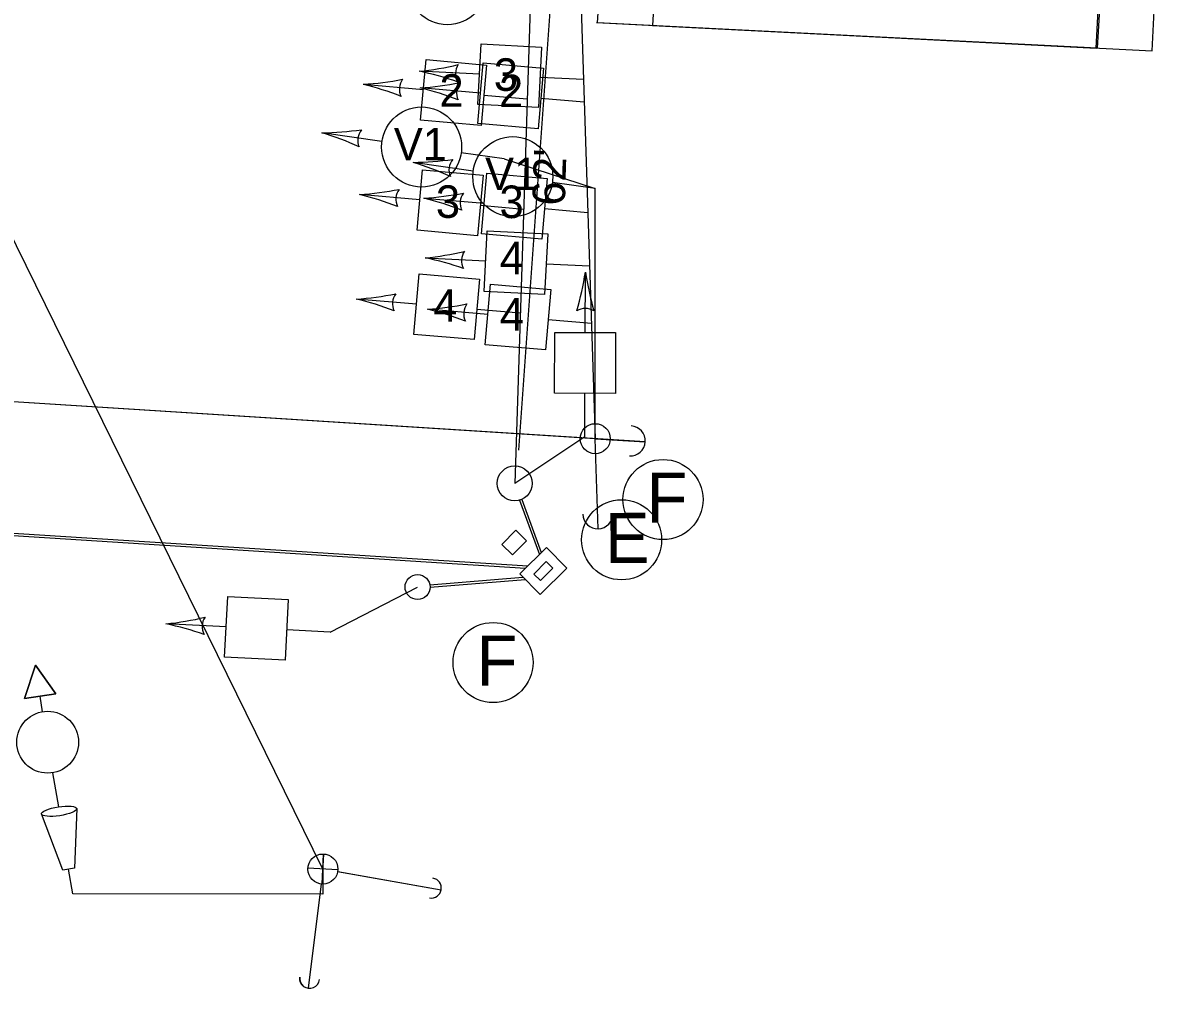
# Model space of a CAD drawing. Extents: x 647787 to 668496, y 640478 to 654412.
# Drawn here: x 659905.1 to 660018.3, y 647331.3 to 647427.8 of the extents above; entities that cross this region are included whole.
import ezdxf

# ---------------------------------------------------------------- set-up
doc = ezdxf.new("R2010")
doc.units = 0
for name, color, linetype in [('T_EXIST_PULL BOX', 7, 'Continuous'), ('TEMP_DETECTION ZONE_STAGE 3', 7, 'Continuous'), ('TEMP_DETECTION_ZONE_STAGE 5', 7, 'Continuous'), ('TEMP_SIGNAL POLES', 7, 'Continuous'), ('TEMP_SIGNAL_HEAD_STAGE 1A', 7, 'Continuous'), ('TEMP_SIGNAL_HEAD_STAGE 2', 7, 'Continuous'), ('TEMP_SIGNAL_HEAD_STAGE 2 SALEM', 7, 'Continuous'), ('TEMP_SIGNAL_HEAD_Stage 3', 7, 'Continuous'), ('TEMP_SIGNAL_HEAD_STAGE 5', 7, 'Continuous'), ('TEMP_SIGNAL_POLES_STAGE 1A', 7, 'Continuous'), ('TEMP_SIGNAL_POLES_STAGE 1B', 7, 'Continuous'), ('TEMP_SIGNAL_POLES_STAGE 2', 7, 'Continuous'), ('TEMP_SIGNAL_POLES_STAGE 3', 7, 'Continuous'), ('TEMP_SIGNAL_POLES_STAGE 5', 7, 'Continuous'), ('TEXT_TEMP_SIGNAL_POLES_STAGE 2', 7, 'Continuous'), ('TEXT_TEMP_SIGNAL_POLES_STAGE 3', 7, 'Continuous'), ('TEXT_TEMP_SIGNAL_POLES_STAGE 4', 7, 'Continuous'), ('TEXT_TEMP_SIGNAL_POLES_STAGE 5', 7, 'Continuous')]:
    doc.layers.add(name, color=color, linetype=linetype)

msp = doc.modelspace()

# ---------------------------------------------------------------- linework, layer by layer
at = {"layer": 'T_EXIST_PULL BOX'}
msp.add_lwpolyline([(659953.01, 647375.66), (659954.41, 647377.09), (659955.48, 647376.03), (659954.07, 647374.61)], close=True, dxfattribs=at)
msp.add_lwpolyline([(659953.01, 647375.66), (659954.41, 647377.09), (659955.48, 647376.03), (659954.07, 647374.61)], close=True, dxfattribs=at)
at = {"layer": 'TEMP_DETECTION ZONE_STAGE 3'}
for p, q in [((659962.57, 647427.78), (659962.91, 647433.77)), ((660012.84, 647431.23), (660012.5, 647425.24)), ((660012.5, 647425.24), (659962.57, 647427.78))]:
    msp.add_line(p, q, dxfattribs=at)
at = {"layer": 'TEMP_DETECTION_ZONE_STAGE 5'}
for p, q in [((659959.03, 647446.07), (659954.66, 647385.09)), ((659959.03, 647446.07), (659954.66, 647385.09)), ((659968.38, 647433.49), (659968.07, 647427.5)), ((660012.4, 647425.25), (660012.7, 647431.24)), ((660018.01, 647424.96), (660018.31, 647430.96)), ((659962.46, 647427.79), (660012.4, 647425.25)), ((659968.07, 647427.5), (660018.01, 647424.96))]:
    msp.add_line(p, q, dxfattribs=at)
at = {"layer": 'TEMP_SIGNAL POLES'}
for p, q in [((659935.12, 647343.23), (659859.63, 647496.63)), ((659935.12, 647343.23), (659859.63, 647496.63)), ((659935.12, 647343.23), (659859.63, 647496.63)), ((659935.12, 647343.23), (659859.63, 647496.63)), ((659935.04, 647341.73), (659935.19, 647344.73)), ((659935.04, 647341.73), (659935.19, 647344.73)), ((659935.04, 647341.73), (659935.19, 647344.73)), ((659935.04, 647341.73), (659935.2, 647344.73)), ((659936.61, 647343.15), (659933.62, 647343.31)), ((659936.61, 647343.15), (659933.62, 647343.31)), ((659936.61, 647343.15), (659933.62, 647343.31)), ((659936.62, 647343.15), (659933.62, 647343.31)), ((659935.12, 647343.23), (659935.12, 647340.73)), ((659935.12, 647343.23), (659935.12, 647340.73)), ((659935.12, 647343.23), (659935.12, 647340.73)), ((659935.12, 647343.23), (659935.12, 647340.73)), ((659936.59, 647342.97), (659946.94, 647341.16)), ((659936.59, 647342.97), (659946.94, 647341.16)), ((659936.59, 647342.97), (659946.94, 647341.16)), ((659936.6, 647342.97), (659946.94, 647341.16)), ((659934.93, 647341.74), (659933.66, 647331.32)), ((659934.93, 647341.74), (659933.66, 647331.32)), ((659934.93, 647341.74), (659933.66, 647331.32)), ((659934.94, 647341.74), (659933.66, 647331.32))]:
    msp.add_line(p, q, dxfattribs=at)
msp.add_lwpolyline([(659935.12, 647340.73), (659910.12, 647340.74)], dxfattribs=at)
msp.add_lwpolyline([(659935.12, 647340.73), (659910.12, 647340.74)], dxfattribs=at)
msp.add_lwpolyline([(659935.12, 647340.73), (659910.12, 647340.74)], dxfattribs=at)
msp.add_lwpolyline([(659935.12, 647340.73), (659910.12, 647340.74)], dxfattribs=at)
msp.add_circle((659935.12, 647343.23), 1.5, dxfattribs=at)
msp.add_circle((659935.12, 647343.23), 1.5, dxfattribs=at)
msp.add_circle((659935.12, 647343.23), 1.5, dxfattribs=at)
msp.add_circle((659935.12, 647343.23), 1.5, dxfattribs=at)
for centre, start, end in [((659945.95, 647341.33), 260.051, 80.051), ((659945.95, 647341.33), 260.051, 80.051), ((659945.95, 647341.33), 260.051, 80.051), ((659945.95, 647341.33), 260.051, 80.051), ((659933.78, 647332.31), 173.0416, 353.0416), ((659933.78, 647332.31), 173.0416, 353.0416), ((659933.78, 647332.31), 173.0416, 353.0416), ((659933.79, 647332.31), 173.0416, 353.0416)]:
    msp.add_arc(centre, 1, start, end, dxfattribs=at)
at = {"layer": 'TEMP_SIGNAL_HEAD_STAGE 1A'}
for p, q in [((659834.95, 647380.92), (659955.37, 647373.29)), ((659834.95, 647380.92), (659955.37, 647373.29)), ((659834.95, 647380.92), (659955.37, 647373.29)), ((659834.96, 647381.17), (659955.61, 647373.52)), ((659834.96, 647381.17), (659955.61, 647373.52)), ((659834.96, 647381.17), (659955.61, 647373.52)), ((659954.77, 647380.07), (659956.75, 647374.65)), ((659954.77, 647380.07), (659956.75, 647374.65)), ((659954.77, 647380.07), (659956.75, 647374.65)), ((659955.01, 647380.16), (659956.94, 647374.85)), ((659955.01, 647380.16), (659956.94, 647374.85)), ((659955.01, 647380.16), (659956.94, 647374.85)), ((659954.79, 647372.71), (659957.45, 647375.35)), ((659954.79, 647372.71), (659957.45, 647375.35)), ((659954.79, 647372.71), (659957.45, 647375.35)), ((659959.5, 647373.28), (659957.45, 647375.35)), ((659959.5, 647373.28), (659957.45, 647375.35)), ((659959.5, 647373.28), (659957.45, 647375.35)), ((659956.2, 647372.7), (659957.44, 647373.94)), ((659956.2, 647372.7), (659957.44, 647373.94)), ((659956.2, 647372.7), (659957.44, 647373.94)), ((659958.09, 647373.29), (659957.44, 647373.94)), ((659958.09, 647373.29), (659957.44, 647373.94)), ((659958.09, 647373.29), (659957.44, 647373.94)), ((659956.84, 647370.64), (659959.5, 647373.28)), ((659956.84, 647370.64), (659959.5, 647373.28)), ((659956.84, 647370.64), (659959.5, 647373.28)), ((659956.85, 647372.05), (659958.09, 647373.29)), ((659956.85, 647372.05), (659958.09, 647373.29)), ((659956.85, 647372.05), (659958.09, 647373.29)), ((659945.81, 647371.63), (659955.11, 647372.39)), ((659945.81, 647371.63), (659955.11, 647372.39)), ((659945.81, 647371.63), (659955.11, 647372.39)), ((659945.83, 647371.38), (659955.34, 647372.16)), ((659945.83, 647371.38), (659955.34, 647372.16)), ((659945.83, 647371.38), (659955.34, 647372.16)), ((659956.84, 647370.64), (659954.79, 647372.71)), ((659956.84, 647370.64), (659954.79, 647372.71)), ((659956.84, 647370.64), (659954.79, 647372.71)), ((659956.85, 647372.05), (659956.2, 647372.7)), ((659956.85, 647372.05), (659956.2, 647372.7)), ((659956.85, 647372.05), (659956.2, 647372.7))]:
    msp.add_line(p, q, dxfattribs=at)
at = {"layer": 'TEMP_SIGNAL_HEAD_STAGE 2'}
for p, q in [((659950.76, 647422.62), (659944.73, 647422.93)), ((659961.16, 647422.09), (659956.82, 647422.31)), ((659950.14, 647412.96), (659944.13, 647413.82)), ((659962.34, 647411.22), (659958.06, 647411.83)), ((659962.34, 647386.22), (659962.34, 647411.22)), ((659951.38, 647403.97), (659945.35, 647404.27)), ((659961.78, 647403.44), (659957.43, 647403.66))]:
    msp.add_line(p, q, dxfattribs=at)
for points in [[(659956.97, 647425.34), (659956.67, 647419.29), (659950.61, 647419.59), (659950.92, 647425.65)], [(659957.59, 647406.69), (659957.28, 647400.63), (659951.23, 647400.94), (659951.53, 647407)]]:
    msp.add_lwpolyline(points, close=True, dxfattribs=at)
msp.add_circle((659954.1, 647412.4), 4, dxfattribs=at)
for centre, radius, start, end in [((659941.8, 647452.25), 29.47, 275.7037, 283.4418), ((659938.85, 647394.05), 29.47, 70.749, 78.4871), ((659949.99, 647422.66), 1.63, 145.2481, 208.9427), ((659943.87, 647443.29), 29.47, 270.5102, 278.2483), ((659935.66, 647385.59), 29.47, 65.5545, 73.2926), ((659949.35, 647413.07), 1.63, 140.0435, 203.7381), ((659942.42, 647433.6), 29.47, 275.7037, 283.4418), ((659950.61, 647404.01), 1.63, 145.2481, 208.9427), ((659939.46, 647375.4), 29.47, 70.749, 78.4871)]:
    msp.add_arc(centre, radius, start, end, dxfattribs=at)
at = {"layer": 'TEMP_SIGNAL_HEAD_STAGE 2 SALEM'}
for points in [[(659908.42, 647360.73), (659905.3, 647360.25), (659906.38, 647363.59), (659908.42, 647360.73)], [(659908.42, 647360.73), (659905.3, 647360.25), (659906.38, 647363.59), (659908.42, 647360.73)], [(659907.1, 647358.94), (659906.86, 647360.49)], [(659907.1, 647358.94), (659906.86, 647360.49)], [(659908.11, 647352.85), (659908.68, 647349.44)], [(659908.11, 647352.85), (659908.68, 647349.44)], [(659910.52, 647349.27), (659910.29, 647343.3)], [(659910.52, 647349.27), (659910.29, 647343.3)], [(659909.14, 647343.12), (659906.98, 647348.73)], [(659909.14, 647343.12), (659906.98, 647348.73)], [(659910.29, 647343.3), (659909.14, 647343.12)], [(659910.29, 647343.3), (659909.14, 647343.12)], [(659910.12, 647340.74), (659909.71, 647343.21)], [(659910.12, 647340.74), (659909.71, 647343.21)]]:
    msp.add_lwpolyline(points, dxfattribs=at)
msp.add_lwpolyline([(659906.38, 647363.59), (659905.3, 647360.25), (659908.42, 647360.73)], close=True, dxfattribs=at)
msp.add_lwpolyline([(659906.38, 647363.59), (659905.3, 647360.25), (659908.42, 647360.73)], close=True, dxfattribs=at)
msp.add_circle((659907.61, 647355.9), 3.09, dxfattribs=at)
msp.add_circle((659907.61, 647355.9), 3.09, dxfattribs=at)
msp.add_ellipse((659908.75, 647349), major_axis=(-1.77, -0.27), ratio=0.249111, dxfattribs=at)
msp.add_ellipse((659908.75, 647349), major_axis=(-1.77, -0.27), ratio=0.249111, dxfattribs=at)
at = {"layer": 'TEMP_SIGNAL_HEAD_Stage 3'}
for p, q in [((659950.86, 647420.74), (659944.85, 647421.27)), ((659961.24, 647419.84), (659956.9, 647420.21)), ((659941.02, 647415.92), (659935.02, 647416.78)), ((659953.23, 647414.18), (659948.94, 647414.79)), ((659953.23, 647414.18), (659962.34, 647411.22)), ((659962.34, 647386.22), (659962.34, 647411.22)), ((659951.23, 647409.71), (659945.21, 647410.23)), ((659961.6, 647408.8), (659957.27, 647409.18)), ((659951.59, 647398.63), (659945.58, 647399.16)), ((659961.96, 647397.73), (659957.63, 647398.11))]:
    msp.add_line(p, q, dxfattribs=at)
for points in [[(659957.17, 647423.24), (659956.64, 647417.19), (659950.6, 647417.72), (659951.13, 647423.76)], [(659957.53, 647412.2), (659957.01, 647406.16), (659950.97, 647406.69), (659951.49, 647412.73)], [(659957.9, 647401.13), (659957.37, 647395.09), (659951.33, 647395.61), (659951.86, 647401.65)]]:
    msp.add_lwpolyline(points, close=True, dxfattribs=at)
msp.add_circle((659944.98, 647415.36), 4, dxfattribs=at)
for centre, radius, start, end in [((659942.98, 647450.68), 29.47, 273.6272, 281.3654), ((659950.09, 647420.81), 1.63, 143.1716, 206.8662), ((659937.92, 647392.62), 29.47, 68.6725, 76.4106), ((659934.75, 647446.25), 29.47, 270.5102, 278.2483), ((659940.23, 647416.03), 1.63, 140.0435, 203.7381), ((659926.54, 647388.55), 29.47, 65.5545, 73.2926), ((659943.35, 647439.65), 29.47, 273.6272, 281.3654), ((659938.29, 647381.59), 29.47, 68.6725, 76.4106), ((659950.46, 647409.78), 1.63, 143.1716, 206.8662), ((659943.71, 647428.57), 29.47, 273.6272, 281.3654), ((659938.65, 647370.51), 29.47, 68.6725, 76.4106), ((659950.82, 647398.7), 1.63, 143.1716, 206.8662)]:
    msp.add_arc(centre, radius, start, end, dxfattribs=at)
at = {"layer": 'TEMP_SIGNAL_HEAD_STAGE 5'}
for p, q in [((659945.16, 647421.07), (659939.14, 647421.62)), ((659945.16, 647421.07), (659939.14, 647421.62)), ((659955.53, 647420.13), (659951.2, 647420.52)), ((659955.53, 647420.13), (659951.2, 647420.52)), ((659944.81, 647410.07), (659938.79, 647410.62)), ((659944.81, 647410.07), (659938.79, 647410.62)), ((659955.17, 647409.13), (659950.85, 647409.52)), ((659955.17, 647409.13), (659950.85, 647409.52)), ((659944.47, 647399.66), (659938.45, 647400.17)), ((659944.47, 647399.66), (659938.45, 647400.17)), ((659954.84, 647398.77), (659950.51, 647399.14)), ((659954.84, 647398.77), (659950.51, 647399.14))]:
    msp.add_line(p, q, dxfattribs=at)
for points in [[(659951.47, 647423.54), (659950.92, 647417.5), (659944.89, 647418.05), (659945.44, 647424.09)], [(659951.47, 647423.54), (659950.92, 647417.5), (659944.89, 647418.05), (659945.44, 647424.09)], [(659951.12, 647412.54), (659950.57, 647406.5), (659944.53, 647407.05), (659945.08, 647413.09)], [(659951.12, 647412.54), (659950.57, 647406.5), (659944.53, 647407.05), (659945.08, 647413.09)], [(659950.77, 647402.16), (659950.25, 647396.12), (659944.21, 647396.64), (659944.73, 647402.68)], [(659950.77, 647402.16), (659950.25, 647396.12), (659944.21, 647396.64), (659944.73, 647402.68)]]:
    msp.add_lwpolyline(points, close=True, dxfattribs=at)
msp.add_circle((659947.56, 647431.58), 4, dxfattribs=at)
msp.add_circle((659947.56, 647431.58), 4, dxfattribs=at)
for centre, radius, start, end in [((659937.39, 647451.04), 29.47, 273.4111, 281.1492), ((659937.39, 647451.04), 29.47, 273.4111, 281.1492), ((659932.11, 647393), 29.47, 68.4564, 76.1945), ((659932.11, 647393), 29.47, 68.4564, 76.1945), ((659944.39, 647421.14), 1.63, 142.9555, 206.6501), ((659944.39, 647421.14), 1.63, 142.9555, 206.6501), ((659937.04, 647440.04), 29.47, 273.4111, 281.1492), ((659937.04, 647440.04), 29.47, 273.4111, 281.1492), ((659931.76, 647382), 29.47, 68.4564, 76.1945), ((659931.76, 647382), 29.47, 68.4564, 76.1945), ((659944.04, 647410.14), 1.63, 142.9555, 206.6501), ((659944.04, 647410.14), 1.63, 142.9555, 206.6501), ((659936.55, 647429.58), 29.47, 273.7041, 281.4422), ((659936.55, 647429.58), 29.47, 273.7041, 281.4422), ((659931.56, 647371.52), 29.47, 68.7494, 76.4875), ((659931.56, 647371.52), 29.47, 68.7494, 76.4875), ((659943.7, 647399.72), 1.63, 143.2485, 206.9431), ((659943.7, 647399.72), 1.63, 143.2485, 206.9431)]:
    msp.add_arc(centre, radius, start, end, dxfattribs=at)
at = {"layer": 'TEMP_SIGNAL_POLES_STAGE 1A'}
for p, q in [((659956.29, 647443.72), (659954.29, 647381.75)), ((659945.16, 647421.07), (659939.14, 647421.62)), ((659955.53, 647420.13), (659951.2, 647420.52)), ((659944.81, 647410.07), (659938.79, 647410.62)), ((659955.17, 647409.13), (659950.85, 647409.52)), ((659961.34, 647396.83), (659961.36, 647402.87)), ((659944.47, 647399.66), (659938.45, 647400.17)), ((659954.84, 647398.77), (659950.51, 647399.14)), ((659961.3, 647386.42), (659961.31, 647390.77)), ((659961.3, 647386.42), (659954.29, 647381.75)), ((659935.85, 647366.89), (659944.58, 647371.4)), ((659925.46, 647367.42), (659919.42, 647367.72)), ((659935.85, 647366.89), (659931.51, 647367.11))]:
    msp.add_line(p, q, dxfattribs=at)
for points in [[(659951.47, 647423.54), (659950.92, 647417.5), (659944.89, 647418.05), (659945.44, 647424.09)], [(659951.12, 647412.54), (659950.57, 647406.5), (659944.53, 647407.05), (659945.08, 647413.09)], [(659950.77, 647402.16), (659950.25, 647396.12), (659944.21, 647396.64), (659944.73, 647402.68)], [(659964.35, 647390.75), (659958.28, 647390.78), (659958.31, 647396.84), (659964.37, 647396.82)], [(659931.66, 647370.14), (659931.36, 647364.08), (659925.3, 647364.39), (659925.61, 647370.44)]]:
    msp.add_lwpolyline(points, close=True, dxfattribs=at)
for centre, radius in [((659947.56, 647431.58), 4), ((659954.29, 647381.75), 1.75), ((659944.58, 647371.4), 1.25)]:
    msp.add_circle(centre, radius, dxfattribs=at)
for centre, radius, start, end in [((659937.39, 647451.04), 29.47, 273.4111, 281.1492), ((659932.11, 647393), 29.47, 68.4564, 76.1945), ((659944.39, 647421.14), 1.63, 142.9555, 206.6501), ((659937.04, 647440.04), 29.47, 273.4111, 281.1492), ((659931.76, 647382), 29.47, 68.4564, 76.1945), ((659944.04, 647410.14), 1.63, 142.9555, 206.6501), ((659932.24, 647407.4), 29.47, 343.4217, 351.1598), ((659990.52, 647407.16), 29.47, 188.3764, 196.1145), ((659936.55, 647429.58), 29.47, 273.7041, 281.4422), ((659931.56, 647371.52), 29.47, 68.7494, 76.4875), ((659943.7, 647399.72), 1.63, 143.2485, 206.9431), ((659961.34, 647397.6), 1.63, 57.9208, 121.6154), ((659916.5, 647397.05), 29.47, 275.6999, 283.438), ((659924.68, 647367.46), 1.63, 145.2443, 208.9389), ((659913.54, 647338.84), 29.47, 70.7451, 78.4833)]:
    msp.add_arc(centre, radius, start, end, dxfattribs=at)
at = {"layer": 'TEMP_SIGNAL_POLES_STAGE 1B'}
for p, q in [((659968.38, 647433.49), (659968.07, 647427.5)), ((660018.01, 647424.96), (660018.31, 647430.96)), ((659968.07, 647427.5), (660018.01, 647424.96))]:
    msp.add_line(p, q, dxfattribs=at)
at = {"layer": 'TEMP_SIGNAL_POLES_STAGE 2'}
for p, q in [((659959.03, 647486.54), (659962.34, 647386.22)), ((659962.34, 647386.22), (659823.61, 647395.02)), ((659962.34, 647386.22), (659967.33, 647385.9)), ((659962.64, 647377.23), (659962.34, 647386.22))]:
    msp.add_line(p, q, dxfattribs=at)
msp.add_circle((659962.34, 647386.22), 1.5, dxfattribs=at)
for centre, start, end in [((659965.84, 647386), 266.372, 86.372), ((659962.59, 647378.72), 181.8894, 1.8894)]:
    msp.add_arc(centre, 1.5, start, end, dxfattribs=at)
at = {"layer": 'TEMP_SIGNAL_POLES_STAGE 3'}
for p, q in [((659959.03, 647486.54), (659962.34, 647386.22)), ((659967.33, 647385.9), (659823.61, 647395.02)), ((659962.34, 647386.22), (659967.33, 647385.9)), ((659962.64, 647377.23), (659962.34, 647386.22))]:
    msp.add_line(p, q, dxfattribs=at)
msp.add_circle((659962.34, 647386.22), 1.5, dxfattribs=at)
for centre, start, end in [((659965.84, 647386), 266.372, 86.372), ((659962.59, 647378.72), 181.8894, 1.8894)]:
    msp.add_arc(centre, 1.5, start, end, dxfattribs=at)
at = {"layer": 'TEMP_SIGNAL_POLES_STAGE 5'}
msp.add_line((659956.29, 647443.72), (659954.29, 647381.75), dxfattribs=at)
msp.add_line((659956.29, 647443.72), (659954.29, 647381.75), dxfattribs=at)
for centre, radius in [((659954.29, 647381.75), 1.75), ((659954.29, 647381.75), 1.75), ((659944.58, 647371.4), 1.25), ((659944.58, 647371.4), 1.25)]:
    msp.add_circle(centre, radius, dxfattribs=at)
at = {"layer": 'TEXT_TEMP_SIGNAL_POLES_STAGE 2'}
msp.add_circle((659969.11, 647380.14), 4, dxfattribs=at)
at = {"layer": 'TEXT_TEMP_SIGNAL_POLES_STAGE 3'}
msp.add_circle((659969.11, 647380.14), 4, dxfattribs=at)
at = {"layer": 'TEXT_TEMP_SIGNAL_POLES_STAGE 4'}
for centre in [(659964.97, 647376.12), (659952.13, 647363.86)]:
    msp.add_circle(centre, 4, dxfattribs=at)
at = {"layer": 'TEXT_TEMP_SIGNAL_POLES_STAGE 5'}
for centre in [(659964.97, 647376.12), (659952.13, 647363.86)]:
    msp.add_circle(centre, 4, dxfattribs=at)

# ---------------------------------------------------------------- texts
at = {"layer": 'TEXT_TEMP_SIGNAL_POLES_STAGE 2'}
for s, p in [('3', (659952.2, 647420.97)), ('4', (659952.8, 647402.64))]:
    msp.add_text(s, height=3.25, dxfattribs=at).set_placement(p)
for s, height, rotation, p in [('V1', 3.25, 359.934, (659951.32, 647411.06)), ('F', 5, 0.1096, (659967.47, 647377.83))]:
    msp.add_text(s, height=height, rotation=rotation, dxfattribs=at).set_placement(p)
at = {"layer": 'TEXT_TEMP_SIGNAL_POLES_STAGE 3'}
for s, p in [('2', (659952.72, 647419.34)), ('3', (659952.77, 647408.26)), ('4', (659952.8, 647397.02))]:
    msp.add_text(s, height=3.25, dxfattribs=at).set_placement(p)
for s, height, rotation, p in [('V1', 3.25, 359.934, (659942.2, 647414.02)), ('F', 5, 0.1096, (659967.47, 647377.83))]:
    msp.add_text(s, height=height, rotation=rotation, dxfattribs=at).set_placement(p)
at = {"layer": 'TEXT_TEMP_SIGNAL_POLES_STAGE 4'}
for s, p in [('2', (659946.77, 647419.38)), ('3', (659946.41, 647408.28)), ('4', (659946.14, 647397.9))]:
    msp.add_text(s, height=3.25, dxfattribs=at).set_placement(p)
for s, height, rotation, p in [("62'", 3.25, 88.1596, (659959.29, 647409.47)), ('E', 5, 0.1096, (659963.32, 647373.81)), ('F', 5, 0.1096, (659950.48, 647361.55))]:
    msp.add_text(s, height=height, rotation=rotation, dxfattribs=at).set_placement(p)
at = {"layer": 'TEXT_TEMP_SIGNAL_POLES_STAGE 5'}
for s, p in [('2', (659946.77, 647419.38)), ('3', (659946.41, 647408.28)), ('4', (659946.14, 647397.9))]:
    msp.add_text(s, height=3.25, dxfattribs=at).set_placement(p)
for s, height, rotation, p in [("62'", 3.25, 88.1596, (659959.29, 647409.47)), ('E', 5, 0.1096, (659963.32, 647373.81)), ('F', 5, 0.1096, (659950.48, 647361.55))]:
    msp.add_text(s, height=height, rotation=rotation, dxfattribs=at).set_placement(p)

doc.saveas('drawing.dxf')
